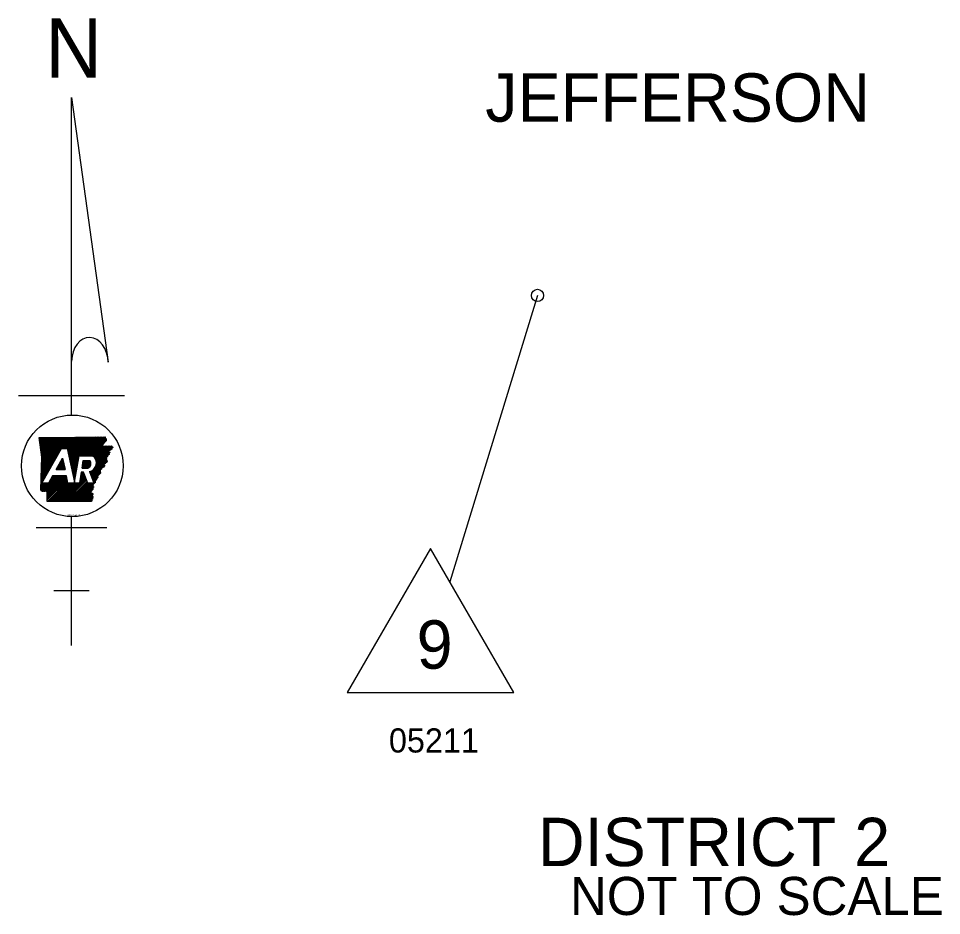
# Model space of a CAD drawing. Extents: x -24122 to 24238, y -8840 to 11381.
# Drawn here: x -12321 to -7743, y -6076 to -1623 of the extents above; entities that cross this region are included whole.
import ezdxf

# ---------------------------------------------------------------- set-up
doc = ezdxf.new("R2010")
doc.units = 0
for name, color, linetype in [('R_Annotation', 7, 'Continuous'), ('R_Border', 7, 'Continuous'), ('R_No Plot', 7, 'Continuous')]:
    doc.layers.add(name, color=color, linetype=linetype)

msp = doc.modelspace()

# ---------------------------------------------------------------- linework, layer by layer
at = {"layer": 'R_Annotation'}
for p, q in [((-12058.1, -2015.7), (-11876.2, -3329.8)), ((-12058.1, -3591.5), (-12058.1, -2015.7)), ((-9746.8, -2997.8), (-10182, -4418.7)), ((-12321.3, -3494.1), (-11795, -3494.1)), ((-12217.7, -3704.4), (-12215.6, -3702.3)), ((-12217, -3710.6), (-12208.6, -3702.3)), ((-12216.2, -3716.8), (-12201.6, -3702.3)), ((-12215.4, -3723), (-12194.7, -3702.3)), ((-12214.6, -3729.2), (-12187.7, -3702.3)), ((-12213.9, -3735.4), (-12180.8, -3702.3)), ((-12213.1, -3741.6), (-12173.8, -3702.3)), ((-12212.3, -3747.8), (-12166.8, -3702.3)), ((-12211.6, -3754), (-12159.9, -3702.3)), ((-12210.8, -3760.2), (-12152.9, -3702.3)), ((-12210, -3766.4), (-12145.9, -3702.3)), ((-12209.2, -3772.6), (-12139, -3702.3)), ((-12208.5, -3778.8), (-12132, -3702.3)), ((-12207.7, -3785), (-12125.1, -3702.3)), ((-12207.5, -3854.4), (-12055.3, -3702.2)), ((-12207.2, -3847.2), (-12062.2, -3702.2)), ((-12207, -3840), (-12069.2, -3702.2)), ((-12206.9, -3791.1), (-12118.1, -3702.3)), ((-12206.8, -3832.8), (-12076.2, -3702.2)), ((-12206.5, -3825.6), (-12083.2, -3702.2)), ((-12206.3, -3818.4), (-12090.2, -3702.2)), ((-12206.2, -3797.3), (-12111.1, -3702.3)), ((-12206, -3811.2), (-12097.1, -3702.3)), ((-12205.8, -3803.9), (-12104.1, -3702.3)), ((-12104, -3757.9), (-12048.3, -3702.2)), ((-12097.1, -3757.9), (-12041.3, -3702.1)), ((-12090.1, -3757.9), (-12034.3, -3702.1)), ((-12083.1, -3757.9), (-12027.2, -3702)), ((-12078.8, -3760.5), (-12020.1, -3701.9)), ((-12077.6, -3766.3), (-12013.1, -3701.8)), ((-12076.3, -3772), (-12006, -3701.6)), ((-12075.1, -3777.7), (-11998.9, -3701.5)), ((-12073.9, -3783.5), (-11991.8, -3701.4)), ((-12072.7, -3789.2), (-11984.8, -3701.3)), ((-12071.4, -3795), (-11977.7, -3701.2)), ((-12070.2, -3800.7), (-11970.6, -3701.1)), ((-12069, -3806.4), (-11963.5, -3701)), ((-12067.7, -3812.2), (-11956.4, -3700.9)), ((-12066.5, -3817.9), (-11949.4, -3700.8)), ((-12065.3, -3823.6), (-11942.3, -3700.7)), ((-12064.1, -3829.4), (-11935.2, -3700.5)), ((-12062.8, -3835.1), (-11928.1, -3700.4)), ((-12014.4, -3793.7), (-11920.9, -3700.2)), ((-12007.5, -3793.7), (-11913.8, -3700)), ((-12000.5, -3793.7), (-11906.7, -3699.9)), ((-11993.5, -3793.7), (-11899.5, -3699.7)), ((-11986.6, -3793.7), (-11892.4, -3699.5)), ((-11979.6, -3793.7), (-11890.9, -3704.9)), ((-11972.6, -3793.7), (-11887.5, -3708.5)), ((-11965.7, -3793.7), (-11886.6, -3714.6)), ((-11958.7, -3793.7), (-11902.5, -3737.5)), ((-11952.4, -3794.3), (-11903.9, -3745.8)), ((-11948.6, -3797.5), (-11896.5, -3745.4)), ((-11945.2, -3801.1), (-11889.2, -3745.1)), ((-11942.2, -3805), (-11881.8, -3744.7)), ((-11939.6, -3809.4), (-11874.5, -3744.3)), ((-11937.5, -3814.2), (-11867.2, -3743.9)), ((-11935.9, -3819.6), (-11860.5, -3744.3)), ((-11934.9, -3825.6), (-11857.3, -3748)), ((-11860.4, -3758.1), (-11854, -3751.7)), ((-12208.2, -3876), (-12131.9, -3799.7)), ((-12207.9, -3868.8), (-12122.8, -3783.7)), ((-12207.7, -3861.6), (-12113.7, -3767.6)), ((-12205.4, -3929.5), (-12108.2, -3757.9)), ((-12108.2, -3757.9), (-12079.4, -3757.9)), ((-12020.7, -3793.7), (-11953.3, -3793.7)), ((-11936.3, -3841), (-11873.1, -3777.7)), ((-11934.9, -3832.5), (-11873.9, -3771.6)), ((-11880.9, -3792.5), (-11872.3, -3783.9)), ((-12208.7, -3890.4), (-12150.1, -3831.8)), ((-12208.4, -3883.2), (-12141, -3815.8)), ((-12133.9, -3862.2), (-12102.1, -3806)), ((-12133.6, -3862.2), (-12097.8, -3826.4)), ((-12126.6, -3862.2), (-12096.6, -3832.1)), ((-12125.3, -3846.9), (-12099, -3820.6)), ((-12119.7, -3862.2), (-12095.3, -3837.8)), ((-12116.2, -3830.8), (-12100.2, -3814.9)), ((-12112.7, -3862.2), (-12094.1, -3843.6)), ((-12107.1, -3814.8), (-12101.5, -3809.1)), ((-12061.6, -3840.9), (-12022.1, -3801.3)), ((-12060.4, -3846.6), (-12023.5, -3809.8)), ((-12059.1, -3852.3), (-12025, -3818.2)), ((-12057.9, -3858.1), (-12026.5, -3826.6)), ((-12056.7, -3863.8), (-12028, -3835.1)), ((-12055.5, -3869.5), (-12029.4, -3843.5)), ((-12006.1, -3854.6), (-11969.4, -3817.9)), ((-12004.6, -3846.2), (-11976.4, -3817.9)), ((-12003.2, -3837.7), (-11983.3, -3817.9)), ((-12001.7, -3829.3), (-11990.3, -3817.9)), ((-12000.2, -3820.9), (-11997.3, -3817.9)), ((-11999.7, -3817.9), (-11968, -3817.9)), ((-11999.1, -3854.6), (-11965.5, -3821)), ((-11992.1, -3854.6), (-11963.2, -3825.6)), ((-11985.2, -3854.6), (-11961.9, -3831.3)), ((-11978.2, -3854.6), (-11962.5, -3838.9)), ((-11965.1, -3883.7), (-11887.9, -3806.4)), ((-11963.2, -3888.7), (-11886.6, -3812.1)), ((-11961.3, -3893.8), (-11885.3, -3817.8)), ((-11959.5, -3898.9), (-11884, -3823.4)), ((-11942.4, -3854), (-11889.2, -3800.8)), ((-11907.8, -3854.2), (-11898, -3844.4)), ((-12209.4, -3912), (-12177.4, -3880)), ((-12209.1, -3904.8), (-12168.3, -3863.9)), ((-12208.9, -3897.6), (-12159.2, -3847.9)), ((-12133.9, -3862.2), (-12090.1, -3862.2)), ((-12105.7, -3862.2), (-12092.9, -3849.3)), ((-12098.8, -3862.2), (-12091.6, -3855)), ((-12091.8, -3862.2), (-12090.4, -3860.8)), ((-12054.2, -3875.3), (-12030.9, -3851.9)), ((-12053, -3881), (-12032.4, -3860.4)), ((-12051.8, -3886.8), (-12033.8, -3868.8)), ((-12050.6, -3892.5), (-12035.3, -3877.3)), ((-12049.3, -3898.2), (-12036.8, -3885.7)), ((-12016.5, -3914.2), (-11992.4, -3890)), ((-12015, -3905.7), (-11994.3, -3885)), ((-12013.5, -3897.3), (-11996.1, -3879.9)), ((-12012.1, -3888.9), (-11998.2, -3874.9)), ((-12010.6, -3880.4), (-12005.1, -3874.9)), ((-11998, -3874.9), (-12009.6, -3874.9)), ((-12006.1, -3854.6), (-11977.2, -3854.6)), ((-11977.8, -3929.5), (-11998, -3874.9)), ((-11969.4, -3872), (-11948.2, -3929.5)), ((-11968.8, -3873.5), (-11966.7, -3871.4)), ((-11967, -3878.6), (-11953.7, -3865.3)), ((-11957.6, -3904), (-11915.8, -3862.2)), ((-11955.7, -3909.1), (-11916.6, -3870)), ((-11953.8, -3914.2), (-11917.4, -3877.7)), ((-12210.9, -3962.3), (-12178.1, -3929.5)), ((-12210.8, -3955.2), (-12185.1, -3929.5)), ((-12210.6, -3948), (-12192, -3929.5)), ((-12210.3, -3940.8), (-12199, -3929.5)), ((-12210.1, -3933.6), (-12204.6, -3928.2)), ((-12209.9, -3926.4), (-12195.6, -3912.1)), ((-12209.6, -3919.2), (-12186.5, -3896.1)), ((-12208.4, -3966.7), (-12135.1, -3893.5)), ((-12172.1, -3929.5), (-12205.4, -3929.5)), ((-12204.2, -3969.5), (-12128.2, -3893.5)), ((-12199.2, -3971.5), (-12121.2, -3893.5)), ((-12190.9, -3970.2), (-12114.2, -3893.5)), ((-12183.9, -3970.1), (-12107.3, -3893.5)), ((-12178.4, -3971.6), (-12100.3, -3893.5)), ((-12178.2, -3985.3), (-12086.4, -3893.5)), ((-12178.2, -3978.3), (-12093.3, -3893.5)), ((-12178.1, -3992.2), (-12082.7, -3896.8)), ((-12178.1, -3999.2), (-12081.5, -3902.5)), ((-12178.1, -4006.1), (-12080.3, -3908.3)), ((-12178.1, -4013.1), (-12079, -3914)), ((-12178, -4019.9), (-12077.8, -3919.7)), ((-12151.7, -3893.5), (-12172.1, -3929.5)), ((-12171, -4019.9), (-12076.6, -3925.5)), ((-12164.2, -3915.6), (-12142.1, -3893.5)), ((-12164.1, -4019.9), (-12073.6, -3929.5)), ((-12157.1, -4019.9), (-12066.7, -3929.5)), ((-12155.1, -3899.5), (-12149.1, -3893.5)), ((-12083.4, -3893.5), (-12151.7, -3893.5)), ((-12150.1, -4020), (-12059.7, -3929.5)), ((-12143.2, -4020), (-12052.7, -3929.5)), ((-12136.2, -4020), (-12045.8, -3929.5)), ((-12129.3, -4020), (-12038.8, -3929.5)), ((-12122.3, -4020), (-12031.8, -3929.5)), ((-12115.4, -4020), (-12024.9, -3929.5)), ((-12108.4, -4020), (-11988.6, -3900.2)), ((-12101.5, -4020), (-11986.7, -3905.3)), ((-12094.5, -4020), (-11984.9, -3910.4)), ((-12087.6, -4020.1), (-11983, -3915.5)), ((-12080.6, -4020.1), (-11981.1, -3920.6)), ((-12019.2, -3929.5), (-12075.7, -3929.5)), ((-12073.6, -4020.1), (-11979.2, -3925.7)), ((-12066.7, -4020.1), (-11976.1, -3929.5)), ((-12059.7, -4020.1), (-11969.1, -3929.5)), ((-12052.8, -4020.1), (-11962.2, -3929.5)), ((-12048.1, -3904), (-12038.2, -3894.1)), ((-12046.9, -3909.7), (-12039.7, -3902.6)), ((-12045.8, -4020.1), (-11955.2, -3929.5)), ((-12045.6, -3915.5), (-12041.2, -3911)), ((-12044.4, -3921.2), (-12042.7, -3919.4)), ((-12038.9, -4020.1), (-11952.9, -3934.1)), ((-12018, -3922.6), (-11990.5, -3895.1)), ((-11948.2, -3929.5), (-11977.8, -3929.5)), ((-11951.9, -3919.3), (-11930.6, -3897.9)), ((-11950.1, -3924.4), (-11933.6, -3907.9)), ((-12031.9, -4020.2), (-11952.6, -3940.8)), ((-12025, -4020.2), (-11952.3, -3947.4)), ((-12018, -4020.2), (-11951.9, -3954.1)), ((-12011.1, -4020.2), (-11963.4, -3972.5)), ((-12004.1, -4020.2), (-11961.2, -3977.3)), ((-11997.2, -4020.2), (-11959.1, -3982.1)), ((-11990.2, -4020.2), (-11956.9, -3987)), ((-11983.2, -4020.2), (-11954.8, -3991.8)), ((-11976.3, -4020.2), (-11953, -3996.9)), ((-11969.3, -4020.3), (-11956.1, -4007.1)), ((-11962.4, -4020.3), (-11959.3, -4017.2)), ((-12058.1, -4735.2), (-12058.1, -4095.6)), ((-12233.5, -4150), (-11882.6, -4150)), ((-12145.8, -4461.6), (-11970.4, -4461.6)), ((-10690.8, -4969.2), (-9864.2, -4969.2))]:
    msp.add_line(p, q, dxfattribs=at)
for points in [[(-12218, -3702.3), (-12121.9, -3702.3), (-12037.5, -3702.1), (-11938.1, -3700.6), (-11892, -3699.5)], [(-12218, -3702.3), (-12121.9, -3702.3), (-12037.6, -3702.1), (-11938.1, -3700.6), (-11892, -3699.5)], [(-12207.4, -3851.7), (-12205.7, -3801), (-12218, -3702.3)], [(-12211.1, -3962.3), (-12205.7, -3801), (-12218, -3702.3)], [(-11861.8, -3743.7), (-11853.5, -3752.4), (-11874.2, -3769.4), (-11872, -3786.6), (-11889.7, -3798.3), (-11883.6, -3824.8), (-11897.4, -3837.3), (-11898.6, -3850.9), (-11915.2, -3856.9), (-11917.8, -3882.5), (-11929.8, -3895.4), (-11935.6, -3914.7), (-11953, -3930.6), (-11951.7, -3958.8), (-11963.6, -3972.1), (-11952.8, -3996.3), (-11960.3, -4020.3)], [(-11906.2, -3745.9), (-11861.1, -3743.6)], [(-11906.2, -3745.9), (-11861.1, -3743.6)], [(-12079.4, -3757.9), (-12043.6, -3924.9), (-12020.7, -3793.7)], [(-12102.1, -3806), (-12090.1, -3862.2)], [(-12006.1, -3854.6), (-11999.7, -3817.9)], [(-12211, -3962.3), (-12207.4, -3851.7)], [(-12009.6, -3874.9), (-12019.2, -3929.5)], [(-12075.7, -3929.5), (-12083.4, -3893.5)], [(-11960.3, -4020.3), (-12178.1, -4019.9), (-12178.2, -3971.8)], [(-11960.3, -4020.3), (-12178.1, -4019.9), (-12178.2, -3971.8)], [(-9864.2, -4969.2), (-10277.5, -4253.3), (-10690.8, -4969.2)]]:
    msp.add_lwpolyline(points, dxfattribs=at)
msp.add_circle((-9746.8, -2997.8), 30.2, dxfattribs=at)
for centre, major_axis, ratio, start_param, end_param in [((-11967.2, -3332.6), (-3.9, 126.3), 0.719778, 4.712385, 7.768526), ((-11978.4, -3829.4), (-43.6, 0), 0.999987, 1.777838, 4.099264), ((-11984.1, -3833.4), (-22.3, 0), 0.999987, 1.887169, 3.90762)]:
    msp.add_ellipse(centre, major_axis=major_axis, ratio=ratio, start_param=start_param, end_param=end_param, dxfattribs=at)
msp.add_ellipse((-12054, -3843.6), major_axis=(252.1, 0), ratio=0.999976, dxfattribs=at)
for points in [[(-11892, -3699.5), (-11891.7, -3702.1), (-11890.9, -3703.5), (-11890.8, -3706), (-11889.7, -3707.1), (-11888, -3708.2), (-11886.5, -3709.9), (-11886.1, -3711.9), (-11886.6, -3713.9), (-11886.7, -3716.3), (-11886.9, -3718.3), (-11887.3, -3720.1), (-11888.7, -3721.6), (-11890.1, -3722.7), (-11891.3, -3723.9), (-11892.2, -3725.3), (-11893.7, -3726.7), (-11895.3, -3728.2), (-11896.6, -3729.5), (-11897.8, -3731.1), (-11898.4, -3733), (-11899.7, -3734.3), (-11900.8, -3735.5), (-11902.3, -3737.1), (-11902.9, -3738.7), (-11904.3, -3740.5), (-11904.6, -3742.3), (-11905.5, -3743.7), (-11905.6, -3744)], [(-11892, -3699.5), (-11891.7, -3702.1), (-11890.8, -3703.5), (-11890.7, -3706), (-11889.7, -3707.1), (-11888, -3708.1), (-11886.4, -3709.9), (-11886.1, -3711.9), (-11886.6, -3714), (-11886.7, -3716.3), (-11886.9, -3718.3), (-11887.3, -3720.1), (-11888.7, -3721.6), (-11890.1, -3722.7), (-11891.3, -3723.9), (-11892.2, -3725.3), (-11893.7, -3726.7), (-11895.3, -3728.2), (-11896.5, -3729.5), (-11897.8, -3731.1), (-11898.4, -3733), (-11899.8, -3734.3), (-11900.8, -3735.5), (-11902.2, -3737.1), (-11903, -3738.7), (-11904.3, -3740.5), (-11904.6, -3742.3), (-11905.5, -3743.7), (-11905.6, -3744)], [(-11861.8, -3743.7), (-11861.1, -3743.6), (-11859.1, -3745.7), (-11858.2, -3747.6), (-11856.9, -3748.5), (-11855.4, -3749.1), (-11854.3, -3750.4), (-11853.5, -3752), (-11853.9, -3753.3), (-11855.6, -3753.4), (-11857.5, -3753.7), (-11859.2, -3753.6), (-11860.7, -3754.8), (-11859.3, -3756.4), (-11857.6, -3757.9), (-11857.1, -3759.5), (-11858.1, -3761), (-11860, -3761.9), (-11861.8, -3762.6), (-11863.5, -3764), (-11864.3, -3765.4), (-11866.1, -3766), (-11868, -3766.5), (-11869.7, -3766.7), (-11871.6, -3767.1), (-11873.4, -3768), (-11874.2, -3769.5), (-11874, -3771.7), (-11874, -3774), (-11872.1, -3774.8), (-11870.4, -3774.8), (-11868.6, -3775.7), (-11868.9, -3777), (-11870.1, -3778.7), (-11871.6, -3780), (-11873.1, -3780.6), (-11874.4, -3781.9), (-11874, -3783.2), (-11872.7, -3783.9), (-11871.8, -3785.3), (-11872, -3786.6), (-11873.4, -3787.5), (-11874.9, -3787.1), (-11876.1, -3785.6), (-11877.3, -3785.2), (-11878.5, -3784.6), (-11879.8, -3785.4), (-11879.8, -3787.1), (-11880.3, -3788.9), (-11879.8, -3790.3), (-11879.4, -3792.2), (-11879.4, -3793.6), (-11879.8, -3795.7), (-11880.9, -3797.8), (-11882, -3798.4), (-11882.6, -3796.2), (-11882.8, -3794.3), (-11883.5, -3793.2), (-11884.4, -3793.2), (-11885.7, -3794.1), (-11887, -3795.5), (-11888.7, -3796.9), (-11889.8, -3798.4), (-11889.2, -3800.2), (-11887.9, -3800.7), (-11886.9, -3800.4), (-11886.4, -3799.2), (-11885.4, -3799), (-11884.4, -3800.9)], [(-11884.4, -3800.9), (-11884.2, -3802.6), (-11885.2, -3804.4), (-11885.6, -3806.2), (-11885.4, -3808.1), (-11887.3, -3809.1), (-11888.9, -3810.3), (-11888, -3811.7), (-11886.2, -3813), (-11884.4, -3814), (-11883.3, -3815.1), (-11883, -3817.5), (-11882.7, -3819), (-11882.1, -3821.2), (-11881.9, -3822.7), (-11882.9, -3824.4), (-11884.2, -3824.8), (-11885.5, -3824.4), (-11887, -3824.3), (-11888.3, -3825.4), (-11889.2, -3827.1), (-11890.1, -3828.8), (-11890.8, -3830.2), (-11891.4, -3831.8), (-11892.7, -3833.6), (-11894.3, -3833.8), (-11896.2, -3834.3), (-11897.3, -3835.6), (-11897.1, -3837.8), (-11896, -3839.3), (-11895.2, -3841.1), (-11894.7, -3842.7), (-11894.9, -3844.8), (-11895.8, -3846.3), (-11896.8, -3847.2), (-11897.3, -3849), (-11898.1, -3850.5), (-11898.8, -3851), (-11900.2, -3850.8), (-11901.8, -3850.5), (-11903.1, -3850.7), (-11904.3, -3851.3), (-11905.6, -3850.9), (-11906.9, -3849.5), (-11908, -3848.4), (-11909.2, -3848), (-11910.4, -3848.6), (-11910.6, -3850.6), (-11910, -3852.6), (-11909.5, -3855.3), (-11910, -3857), (-11910.2, -3859.8)], [(-11910.2, -3859.8), (-11912.3, -3861.3), (-11913.2, -3863), (-11918.5, -3862.5), (-11918.4, -3864.4), (-11920.2, -3865.3), (-11921.9, -3866.5), (-11921, -3868), (-11919.2, -3869.3), (-11917.4, -3870.3), (-11916.3, -3871.3), (-11916, -3873.8), (-11915.7, -3875.3), (-11915.1, -3877.5), (-11914.8, -3878.9), (-11915.9, -3880.7), (-11917.2, -3881), (-11918.5, -3880.6), (-11920, -3880.5), (-11921.2, -3881.7), (-11922.1, -3883.4), (-11923, -3885.1), (-11923.7, -3886.5), (-11924.4, -3888), (-11925.6, -3889.8), (-11927.2, -3890.1), (-11929.2, -3890.6), (-11930.3, -3891.8), (-11930.1, -3894.1), (-11929, -3895.5), (-11928.2, -3897.4), (-11927.6, -3899), (-11927.9, -3901), (-11928.7, -3902.5), (-11929.8, -3903.4), (-11930.3, -3905.3), (-11931.1, -3906.7), (-11931.8, -3907.2), (-11933.2, -3907), (-11934.7, -3906.8), (-11936, -3906.9), (-11937.3, -3907.5), (-11938.5, -3907.1), (-11939.9, -3905.7), (-11940.9, -3904.6), (-11942.1, -3904.2), (-11943.4, -3904.9), (-11943.6, -3906.8), (-11943, -3908.8), (-11942.5, -3911.6), (-11943, -3913.2), (-11943.2, -3916)], [(-11943.2, -3916), (-11943.3, -3916.1), (-11944.4, -3917.4), (-11943.8, -3919.5), (-11941.5, -3920.4), (-11940.4, -3922.4), (-11940.4, -3924.1), (-11941.1, -3926.6), (-11942.2, -3927.7), (-11944.3, -3928.2), (-11945.9, -3928.5), (-11946.1, -3931.2), (-11946.8, -3932.6), (-11948.1, -3933), (-11949.9, -3932.1), (-11950.9, -3931.7), (-11952.2, -3931.1), (-11953.9, -3930.1), (-11955.2, -3930.3), (-11954.8, -3932.9), (-11954.7, -3933), (-11953.2, -3935), (-11951.8, -3936.5), (-11951.2, -3938.4)], [(-11943.2, -3916), (-11943.3, -3916.1), (-11944.4, -3917.4), (-11943.8, -3919.5), (-11941.5, -3920.4), (-11940.4, -3922.4), (-11940.4, -3924.1), (-11941.1, -3926.6), (-11942.2, -3927.7), (-11944.3, -3928.2), (-11945.9, -3928.5), (-11946.1, -3931.2), (-11946.8, -3932.6), (-11948.1, -3933), (-11949.9, -3932.1), (-11950.9, -3931.7), (-11952.2, -3931.1), (-11953.9, -3930.1), (-11955.2, -3930.3), (-11954.8, -3932.9), (-11954.7, -3933), (-11953.2, -3935), (-11951.8, -3936.5), (-11951.2, -3938.4)], [(-12178.2, -3971.8), (-12177.9, -3972), (-12179.1, -3971.2), (-12180.6, -3970.4), (-12182.3, -3970.3), (-12184.5, -3970), (-12186.4, -3969.8), (-12188.3, -3968.6), (-12190.3, -3969.9), (-12192.6, -3970.8), (-12193.9, -3969.8), (-12195.6, -3970.5), (-12196.8, -3970.1), (-12198.9, -3971.5), (-12200.8, -3971), (-12202.3, -3971.4), (-12204, -3971.4), (-12204.4, -3969.3), (-12206.1, -3969), (-12207.6, -3968.2), (-12208.6, -3966.1), (-12209.3, -3964.5), (-12211.1, -3962.3)], [(-12178.2, -3971.8), (-12177.9, -3971.9), (-12179.1, -3971.2), (-12180.6, -3970.4), (-12182.4, -3970.3), (-12184.6, -3970), (-12186.4, -3969.8), (-12188.3, -3968.6), (-12190.3, -3969.8), (-12192.6, -3970.8), (-12193.9, -3969.7), (-12195.6, -3970.5), (-12196.8, -3970.1), (-12198.9, -3971.5), (-12200.8, -3971), (-12202.2, -3971.4), (-12204, -3971.4), (-12204.4, -3969.3), (-12206.1, -3969.1), (-12207.6, -3968.2), (-12208.6, -3966.1), (-12209.3, -3964.5), (-12211, -3962.3)], [(-11951.2, -3938.4), (-11951.7, -3939.8), (-11952.4, -3942.1), (-11952.2, -3944.1), (-11951.3, -3945.8), (-11949.9, -3946.8), (-11948.3, -3948.2), (-11948.5, -3950.3), (-11949.4, -3951), (-11951.5, -3950.5), (-11953.1, -3949.8), (-11954.4, -3950.2), (-11956.2, -3951.1), (-11957.6, -3951.3), (-11957.6, -3954.1), (-11955.8, -3956.1), (-11954.2, -3956.1), (-11952.3, -3956.4), (-11951.6, -3958.5), (-11952.7, -3960.3), (-11954.5, -3961.2), (-11956.7, -3960.1), (-11958.3, -3959), (-11959.9, -3957.9), (-11962, -3957.4), (-11963.1, -3957.6), (-11963.6, -3960.1), (-11962.7, -3962.4), (-11961.2, -3963.9), (-11959.7, -3965.9), (-11959.9, -3967.5), (-11961, -3967.8), (-11962.9, -3968.3), (-11964.1, -3968.8), (-11964.3, -3969.3), (-11963.8, -3971.4), (-11963.2, -3973.5), (-11963.2, -3975.2), (-11963.9, -3976.7), (-11964.9, -3979.1), (-11964.8, -3980.6), (-11964.1, -3981.4), (-11963.2, -3981.2), (-11962, -3980.3), (-11961.2, -3979.4), (-11960.5, -3978.2), (-11959.3, -3977.2), (-11957.8, -3978.1), (-11957.4, -3979.9), (-11958.3, -3981.5), (-11959.6, -3982.3), (-11961.1, -3982.8), (-11962.2, -3984.1), (-11961.9, -3985.7), (-11961, -3986.5), (-11958.8, -3986.1), (-11957.4, -3985.4), (-11956.5, -3984.6), (-11955.5, -3983.6), (-11955, -3982.6), (-11954.2, -3981.5), (-11952.8, -3981.2), (-11952.2, -3982.1), (-11952.4, -3984.1), (-11953.2, -3986.1), (-11954.4, -3987.6), (-11955.6, -3988.7), (-11957.2, -3991.2), (-11956.9, -3993.4), (-11956.2, -3995.3), (-11955.5, -3996.7), (-11954, -3996.4), (-11952.4, -3996.3), (-11951.5, -3997), (-11951.6, -3998.7), (-11952.8, -4000.3), (-11953.9, -4001.9), (-11954.5, -4004), (-11954.2, -4005.5), (-11954.2, -4006.8), (-11954.7, -4008.3), (-11955.5, -4009.2), (-11957.8, -4009.1), (-11960.1, -4008.9), (-11961.3, -4009.6), (-11961.1, -4011.6), (-11959.7, -4013.1), (-11958.8, -4013.8), (-11957.4, -4015.5), (-11956.8, -4016.9), (-11957, -4018.1), (-11957.9, -4019.1), (-11960.3, -4020.3)], [(-11951.2, -3938.4), (-11951.7, -3939.8), (-11952.4, -3942.1), (-11952.2, -3944.1), (-11951.3, -3945.8), (-11949.9, -3946.8), (-11948.3, -3948.2), (-11948.5, -3950.3), (-11949.4, -3951), (-11951.5, -3950.5), (-11953.1, -3949.8), (-11954.4, -3950.2), (-11956.2, -3951.1), (-11957.6, -3951.3), (-11957.6, -3954.1), (-11955.8, -3956.1), (-11954.2, -3956.1), (-11952.3, -3956.4), (-11951.6, -3958.5), (-11952.7, -3960.3), (-11954.5, -3961.2), (-11956.7, -3960.1), (-11958.3, -3959), (-11959.9, -3957.9), (-11962, -3957.4), (-11963.1, -3957.6), (-11963.6, -3960.1), (-11962.7, -3962.4), (-11961.2, -3963.9), (-11959.7, -3965.9), (-11959.9, -3967.5), (-11961, -3967.8), (-11962.9, -3968.3), (-11964.1, -3968.8), (-11964.3, -3969.3), (-11963.8, -3971.4), (-11963.2, -3973.5), (-11963.2, -3975.2), (-11963.9, -3976.7), (-11964.9, -3979.1), (-11964.8, -3980.6), (-11964.1, -3981.4), (-11963.2, -3981.2), (-11962, -3980.3), (-11961.2, -3979.4), (-11960.5, -3978.2), (-11959.3, -3977.2), (-11957.8, -3978.1), (-11957.4, -3979.9), (-11958.3, -3981.5), (-11959.6, -3982.3), (-11961.1, -3982.8), (-11962.2, -3984.1), (-11961.9, -3985.7), (-11961, -3986.5), (-11958.8, -3986.1), (-11957.4, -3985.4), (-11956.5, -3984.6), (-11955.5, -3983.6), (-11955, -3982.6), (-11954.2, -3981.5), (-11952.8, -3981.2), (-11952.2, -3982.1), (-11952.4, -3984.1), (-11953.2, -3986.1), (-11954.4, -3987.6), (-11955.6, -3988.7), (-11957.2, -3991.2), (-11956.9, -3993.4), (-11956.2, -3995.3), (-11955.5, -3996.7), (-11954, -3996.4), (-11952.4, -3996.3), (-11951.5, -3997), (-11951.6, -3998.7), (-11952.8, -4000.3), (-11953.9, -4001.9), (-11954.5, -4004), (-11954.2, -4005.5), (-11954.2, -4006.8), (-11954.7, -4008.3), (-11955.5, -4009.2), (-11957.8, -4009.1), (-11960.1, -4008.9), (-11961.3, -4009.6), (-11961.1, -4011.6), (-11959.7, -4013.1), (-11958.8, -4013.8), (-11957.4, -4015.5), (-11956.8, -4016.9), (-11957, -4018.1), (-11957.9, -4019.1), (-11960.3, -4020.3)]]:
    msp.add_spline(points, degree=3, dxfattribs=at)

# ---------------------------------------------------------------- texts
for s, height, p in [('N', 293.3, (-12188.8, -1916.5)), ('STS 10-03-17', 7.288, (-12078.1, -4093.6)), ('9', 240, (-10346.5, -4850.5)), ('DISTRICT 2', 240, (-9745.1, -5830.3))]:
    msp.add_text(s, height=height, dxfattribs=at).set_placement(p)
at = {"layer": 'R_Border'}
for s, height, p in [('JEFFERSON', 240, (-10006, -2135.7)), ('NOT TO SCALE', 189, (-9585.8, -6072.9))]:
    msp.add_text(s, height=height, dxfattribs=at).set_placement(p)
at = {"layer": 'R_No Plot'}
msp.add_text('05211', height=120, dxfattribs=at).set_placement((-10484, -5266.5))

doc.saveas('drawing.dxf')
